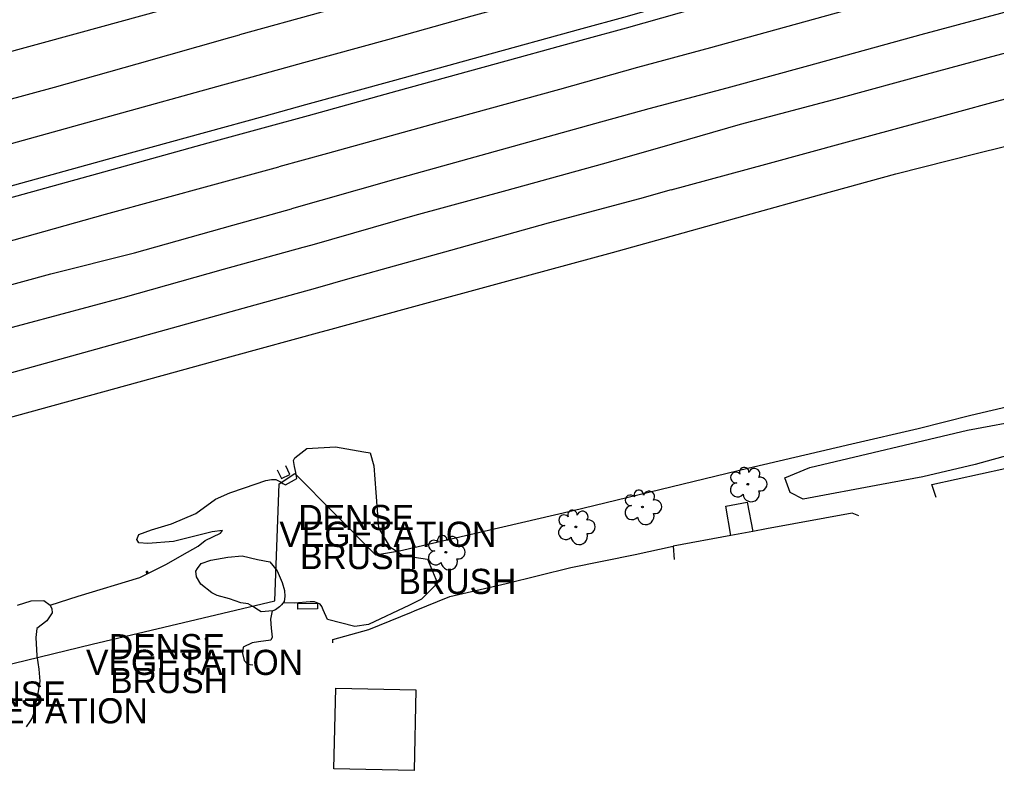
# Model space of a CAD drawing. Extents: x 2129547 to 2134906, y 657330 to 659734.
# Drawn here: x 2130826.3 to 2131098, y 657907.3 to 658118.5 of the extents above; entities that cross this region are included whole.
import ezdxf

# ---------------------------------------------------------------- set-up
doc = ezdxf.new("R2010")
doc.units = 0
for name, color, linetype in [('BD_X_Building', 7, 'Continuous'), ('Default', 7, 'Continuous'), ('DR_X_Culvert', 7, 'Continuous'), ('DR_X_Drainage_Area', 7, 'Continuous'), ('PM_X_Edge_Line', 7, 'Continuous'), ('PM_X_Lane_Line', 7, 'Continuous'), ('PM_X_LaneDOT', 7, 'Continuous'), ('PV_X_Driveway', 7, 'Continuous'), ('PV_X_EOP2', 7, 'Continuous'), ('PV_X_Parking_Lot', 7, 'Continuous'), ('RD_X_Concrete_Barrier', 7, 'Continuous'), ('RD_X_Concrete_Pad', 7, 'Continuous'), ('RD_X_Fence', 7, 'Continuous'), ('RD_X_Noise_Wall', 7, 'Continuous'), ('VG_X_Cells', 7, 'Continuous'), ('VG_X_Shrub_Line_Lt', 7, 'Continuous'), ('VG_X_Text', 7, 'Continuous'), ('VG_X_Tree_Line_Lt', 7, 'Continuous')]:
    doc.layers.add(name, color=color, linetype=linetype)

# ---------------------------------------------------------------- blocks, each defined once
blk = doc.blocks.new('TREE')
at = {"layer": 'VG_X_Cells'}
blk.add_circle((0, 0), 0.00305, dxfattribs=at)
for centre, radius, start, end in [((-0.042, 0.0237), 0.0187, 39.0625, 279.5412), ((-0.0125, 0.0428), 0.0167, 354.0047, 205.9741), ((0.0232, 0.0359), 0.0197, 323.83, 165.0376), ((-0.0362, -0.0197), 0.0251, 96.1722, 320.5737), ((0.0439, 0.0005), 0.0243, 259.1453, 101.4596), ((0.012, -0.0331), 0.029, 184.9476, 19.4572)]:
    blk.add_arc(centre, radius, start, end, dxfattribs=at)
blk = doc.blocks.new('PIPE')
at = {"layer": 'Default'}
for p, q in [((0.135, 0.067), (0, 0.067)), ((0, 0.067), (0, -0.067)), ((0, -0.067), (0.135, -0.067))]:
    blk.add_line(p, q, dxfattribs=at)

msp = doc.modelspace()

# ---------------------------------------------------------------- linework, layer by layer
at = {"layer": 'BD_X_Building'}
msp.add_lwpolyline([(2130914.24, 657932.69), (2130936.54, 657932.19), (2130936.04, 657909.78), (2130913.74, 657910.28)], close=True, dxfattribs=at)
at = {"layer": 'DR_X_Culvert'}
msp.add_lwpolyline([(2130903.73, 657956.21), (2130909.15, 657956.25), (2130909.16, 657954.68), (2130903.74, 657954.64)], close=True, dxfattribs=at)
at = {"layer": 'DR_X_Drainage_Area'}
msp.add_lwpolyline([(2131081.23, 657985.67), (2131079.99, 657989.28), (2131107.11, 657995.18), (2131138.13, 658002.86), (2131172.93, 658011.4), (2131184.68, 658014.24), (2131206.78, 658016.4), (2131235.33, 658019.59)], dxfattribs=at)
at = {"layer": 'PM_X_Edge_Line'}
for points in [[(2130891, 658102.57), (2130905.36, 658106.57), (2130928.7, 658112.95), (2130952.19, 658119.5), (2130974.68, 658125.71), (2130991.22, 658130.21), (2131011.99, 658135.88), (2131037.88, 658143.01), (2131060.83, 658149.3), (2131082.78, 658155.22), (2131106.25, 658161.71), (2131128.24, 658167.69), (2131156.14, 658175.52), (2131181.21, 658182.49), (2131205.87, 658189.24), (2131228.59, 658195.53), (2131252.79, 658202.27), (2131273.67, 658208.13), (2131298.68, 658214.86), (2131324.12, 658221.75), (2131348.82, 658228.57), (2131375.1, 658235.74), (2131400.81, 658242.88)], [(2131391.93, 658213.4), (2131368, 658206.91), (2131341.78, 658199.75), (2131315.24, 658192.47), (2131285.72, 658184.3), (2131257.55, 658176.45), (2131231.68, 658169.56), (2131212.62, 658164.32), (2131190.64, 658158.19), (2131169.84, 658152.49), (2131145.7, 658145.83), (2131125.75, 658140.27), (2131100.74, 658133.28), (2131080.69, 658127.69), (2131055.04, 658120.76), (2131018.49, 658110.67), (2130998.15, 658105.13), (2130976.5, 658099.09), (2130942.37, 658089.65), (2130912.01, 658081.31), (2130898.43, 658077.6)], [(2129783, 657797.65), (2129820.8, 657807.78), (2129922.27, 657836.17), (2129994.45, 657856.25), (2130028.21, 657865.49), (2130093.84, 657883.42), (2130153.98, 657899.99), (2130199.12, 657912.39), (2130249.09, 657926.31), (2130302.49, 657941.01), (2130341.07, 657951.58), (2130345.17, 657952.7), (2130404.65, 657969.17), (2130458.77, 657984.04), (2130511.95, 657998.61), (2130564.35, 658012.89), (2130611.28, 658025.79), (2130665.46, 658040.53), (2130717.36, 658054.84), (2130762.68, 658067.32), (2130806.63, 658079.2), (2130851.4, 658091.68), (2130882.88, 658100.31), (2130891, 658102.57)], [(2130911.96, 658032.18), (2130933.97, 658038.2), (2130961.85, 658045.78), (2130991.21, 658053.76), (2131010.83, 658059.23), (2131028.09, 658064.06), (2131048.8, 658069.77), (2131070.04, 658075.58), (2131092.36, 658081.28), (2131108.42, 658085.27)], [(2129782.31, 657770.56), (2129838.02, 657785.8), (2129918.94, 657807.73), (2130006.57, 657832.43), (2130060.5, 657847.21), (2130112.38, 657861.87), (2130166.66, 657876.43), (2130223.01, 657891.92), (2130282.32, 657908.07), (2130309.12, 657915.87), (2130347.7, 657926.43), (2130352.07, 657927.63), (2130411.57, 657944.11), (2130465.65, 657958.97), (2130518.8, 657973.53), (2130571.22, 657987.81), (2130618.14, 658000.71), (2130672.33, 658015.45), (2130724.27, 658029.78), (2130769.53, 658042.24), (2130813.51, 658054.13), (2130850.23, 658064.39), (2130880.11, 658072.6), (2130898.43, 658077.6)], [(2130514.96, 657935.23), (2130533.56, 657939.51), (2130548.13, 657942.33), (2130572.12, 657946.01), (2130593.17, 657948.82), (2130613.14, 657951.57), (2130630.34, 657955.2), (2130643.38, 657958.22), (2130656.02, 657961.69), (2130694.77, 657972.7), (2130735.95, 657984.14), (2130780.51, 657996.29), (2130819.12, 658006.73), (2130865.97, 658019.55), (2130885.83, 658025.06), (2130910.2, 658031.7), (2130911.96, 658032.18)]]:
    msp.add_lwpolyline(points, dxfattribs=at)
at = {"layer": 'PM_X_Lane_Line'}
for points in [[(2131394.23, 658253.22), (2131371.64, 658247.1), (2131347.48, 658240.52), (2131325.08, 658234.28), (2131302.56, 658228.11), (2131279.27, 658221.78), (2131255.34, 658215.2), (2131230.51, 658208.32), (2131202.78, 658200.44), (2131175.2, 658193.07), (2131142.99, 658184.04), (2131119.15, 658177.56), (2131092.27, 658170.26), (2131066.31, 658163.11), (2131037.76, 658155.51), (2131013.74, 658149.02), (2130988.03, 658141.76), (2130968.64, 658136.39), (2130940.36, 658128.62), (2130910.43, 658120.51), (2130887.53, 658114.21)], [(2131398.2, 658202.88), (2131377.59, 658197.24), (2131355.03, 658191.01), (2131329.48, 658184), (2131308.98, 658178.3), (2131287.17, 658172.05), (2131268.54, 658166.95), (2131249.14, 658161.71), (2131232.12, 658156.84), (2131210.13, 658150.71), (2131191.34, 658145.6), (2131170.47, 658139.83), (2131150.51, 658134.32), (2131128.13, 658128.26), (2131104.27, 658121.56), (2131076.93, 658114.27), (2131045.67, 658105.64), (2131023.04, 658099.46), (2131001.31, 658093.68), (2130986.21, 658089.5), (2130954.6, 658080.73), (2130930.95, 658074.11), (2130910.13, 658068.18), (2130901.91, 658065.91)], [(2131411.36, 658195.07), (2131385.77, 658188.02), (2131365.07, 658182.24), (2131339.74, 658175.46), (2131317.81, 658169.03), (2131291.94, 658161.94), (2131264.7, 658154.39), (2131240.9, 658147.6), (2131216.24, 658140.85), (2131193.46, 658134.43), (2131170.64, 658127.88), (2131144.22, 658120.81), (2131121.64, 658114.69), (2131098.02, 658108.51), (2131078.46, 658103.25), (2131054.06, 658096.57), (2131026.75, 658089.3), (2131004.3, 658082.86), (2130988.32, 658078.33), (2130961.86, 658070.94), (2130936.23, 658064.05), (2130907.59, 658055.8), (2130905.13, 658055.12)], [(2130517.26, 658025.11), (2130555.6, 658035.62), (2130596.09, 658046.96), (2130635.43, 658057.75), (2130673, 658068.21), (2130712.86, 658079.14), (2130754.47, 658090.52), (2130796.26, 658102.11), (2130842.82, 658114.83), (2130877.34, 658124.38), (2130883.95, 658126.23)], [(2130499.23, 658007.56), (2130538.61, 658018.28), (2130576.6, 658028.77), (2130618.67, 658040.36), (2130652.58, 658049.68), (2130692.07, 658060.48), (2130730.09, 658071.06), (2130768.24, 658081.36), (2130807.99, 658092.09), (2130836.01, 658099.68), (2130859, 658106.14), (2130884.83, 658113.47), (2130887.53, 658114.21)], [(2130526.03, 657962.85), (2130563.47, 657973.17), (2130601.11, 657983.57), (2130640.45, 657994.25), (2130678.58, 658004.73), (2130718.03, 658015.65), (2130757.3, 658026.31), (2130795.99, 658037.18), (2130835.05, 658047.79), (2130858.29, 658053.7), (2130885.63, 658061.39), (2130901.91, 658065.91)], [(2130905.13, 658055.12), (2130882.94, 658049.03), (2130855.07, 658041.17), (2130792.06, 658024.31), (2130751.21, 658013.06), (2130713.04, 658002.57), (2130674.42, 657991.9), (2130634.64, 657981.1), (2130596.28, 657970.59), (2130557.28, 657959.92), (2130518.18, 657949.28)]]:
    msp.add_lwpolyline(points, dxfattribs=at)
at = {"layer": 'PM_X_LaneDOT'}
for points in [[(2131007.54, 658071.14), (2131033.85, 658078.34), (2131056.59, 658084.53), (2131076.06, 658089.79), (2131097.73, 658095.69), (2131119.36, 658101.43), (2131140.64, 658107.17), (2131161.55, 658113.24)], [(2131007.54, 658071.14), (2130998.74, 658068.68), (2130973.29, 658061.89), (2130946.17, 658054.29), (2130918.18, 658046.48), (2130908.51, 658043.78)], [(2130908.51, 658043.78), (2130890.08, 658038.64), (2130533.56, 657939.51)]]:
    msp.add_lwpolyline(points, dxfattribs=at)
at = {"layer": 'PV_X_Driveway'}
for points in [[(2130935.32, 657953.77), (2130936.2, 657954.12), (2130946, 657958.15), (2130961.64, 657961.75), (2130979.67, 657966.18), (2130997.56, 657969.82), (2131008.07, 657972.13)], [(2130913.45, 657945.25), (2130913.43, 657946.24), (2130923.46, 657948.99), (2130935.32, 657953.77)]]:
    msp.add_lwpolyline(points, dxfattribs=at)
at = {"layer": 'PV_X_EOP2'}
for points in [[(2130891, 658102.57), (2130905.36, 658106.57), (2130928.7, 658112.95), (2130952.19, 658119.5), (2130974.68, 658125.71), (2130991.22, 658130.21), (2131011.99, 658135.88), (2131037.88, 658143.01), (2131060.83, 658149.3), (2131082.78, 658155.22), (2131106.25, 658161.71), (2131128.24, 658167.69), (2131156.14, 658175.52), (2131181.21, 658182.49), (2131205.87, 658189.24), (2131228.59, 658195.53), (2131252.79, 658202.27), (2131273.67, 658208.13), (2131298.68, 658214.86), (2131324.12, 658221.75), (2131348.82, 658228.57), (2131375.1, 658235.74), (2131400.81, 658242.88)], [(2131391.93, 658213.4), (2131368, 658206.91), (2131341.78, 658199.75), (2131315.24, 658192.47), (2131285.72, 658184.3), (2131257.55, 658176.45), (2131231.68, 658169.56), (2131212.62, 658164.32), (2131190.64, 658158.19), (2131169.84, 658152.49), (2131145.7, 658145.83), (2131125.75, 658140.27), (2131100.74, 658133.28), (2131080.69, 658127.69), (2131055.04, 658120.76), (2131018.49, 658110.67), (2130998.15, 658105.13), (2130976.5, 658099.09), (2130942.37, 658089.65), (2130912.01, 658081.31), (2130898.43, 658077.6)], [(2129783, 657797.65), (2129820.8, 657807.78), (2129922.27, 657836.17), (2129994.45, 657856.25), (2130028.21, 657865.49), (2130093.84, 657883.42), (2130153.98, 657899.99), (2130199.12, 657912.39), (2130249.09, 657926.31), (2130302.49, 657941.01), (2130341.07, 657951.58), (2130345.17, 657952.7), (2130404.65, 657969.17), (2130458.77, 657984.04), (2130511.95, 657998.61), (2130564.35, 658012.89), (2130611.28, 658025.79), (2130665.46, 658040.53), (2130717.36, 658054.84), (2130762.68, 658067.32), (2130806.63, 658079.2), (2130851.4, 658091.68), (2130882.88, 658100.31), (2130891, 658102.57)], [(2130911.96, 658032.18), (2130933.97, 658038.2), (2130961.85, 658045.78), (2130991.21, 658053.76), (2131010.83, 658059.23), (2131028.09, 658064.06), (2131048.8, 658069.77), (2131070.04, 658075.58), (2131092.36, 658081.28), (2131108.42, 658085.27), (2131129.89, 658090.28), (2131149.34, 658094.56), (2131164.37, 658097.66)], [(2129782.31, 657770.56), (2129838.02, 657785.8), (2129918.94, 657807.73), (2130006.57, 657832.43), (2130060.5, 657847.21), (2130112.38, 657861.87), (2130166.66, 657876.43), (2130223.01, 657891.92), (2130282.32, 657908.07), (2130309.12, 657915.87), (2130347.7, 657926.43), (2130352.07, 657927.63), (2130411.57, 657944.11), (2130465.65, 657958.97), (2130518.8, 657973.53), (2130571.22, 657987.81), (2130618.14, 658000.71), (2130672.33, 658015.45), (2130724.27, 658029.78), (2130769.53, 658042.24), (2130813.51, 658054.13), (2130850.23, 658064.39), (2130880.11, 658072.6), (2130898.43, 658077.6)], [(2130514.96, 657935.23), (2130533.56, 657939.51), (2130548.13, 657942.33), (2130572.12, 657946.01), (2130593.17, 657948.82), (2130613.14, 657951.57), (2130630.34, 657955.2), (2130643.38, 657958.22), (2130656.02, 657961.69), (2130694.77, 657972.7), (2130735.95, 657984.14), (2130780.51, 657996.29), (2130819.12, 658006.73), (2130865.97, 658019.55), (2130885.83, 658025.06), (2130910.2, 658031.7), (2130911.96, 658032.18)]]:
    msp.add_lwpolyline(points, dxfattribs=at)
at = {"layer": 'PV_X_Parking_Lot'}
msp.add_lwpolyline([(2131059.67, 657980.58), (2131057.85, 657981.27), (2131034.07, 657976.95), (2131030.19, 657976.23), (2131024.14, 657975.11), (2131008.07, 657972.13), (2131008.32, 657968.47)], dxfattribs=at)
at = {"layer": 'RD_X_Concrete_Barrier'}
for points in [[(2131391.74, 658229.13), (2131379.32, 658225.19), (2131359.92, 658219.83), (2131338.36, 658213.96), (2131312.24, 658206.8), (2131285.52, 658199.37), (2131257.25, 658191.69), (2131234.72, 658185.34), (2131209.47, 658178.52), (2131183.51, 658171.23), (2131159.15, 658164.59), (2131135.07, 658158.08), (2131111.97, 658151.63), (2131085.68, 658144.48), (2131061.03, 658137.57), (2131037, 658130.96), (2131013.95, 658124.67), (2130994.29, 658119.1), (2130982.69, 658115.91), (2130954.42, 658108.17), (2130930.56, 658101.55), (2130905.86, 658094.77), (2130894.27, 658091.58)], [(2130895.13, 658088.7), (2130906.66, 658091.87), (2130931.36, 658098.66), (2130955.21, 658105.28), (2130983.48, 658113.02), (2130995.09, 658116.21), (2131014.76, 658121.78), (2131037.79, 658128.06), (2131061.83, 658134.68), (2131086.48, 658141.59), (2131112.76, 658148.74), (2131135.87, 658155.19), (2131159.93, 658161.69), (2131184.31, 658168.34), (2131210.27, 658175.63), (2131235.52, 658182.45), (2131258.05, 658188.8), (2131286.32, 658196.47), (2131313.04, 658203.91), (2131339.15, 658211.07), (2131360.71, 658216.94), (2131380.03, 658222.28), (2131393.19, 658225.09)], [(2130894.27, 658091.58), (2130878, 658087.11), (2130853.36, 658080.31), (2130816.1, 658070.01), (2130782.91, 658060.82), (2130737.86, 658048.46), (2130695.16, 658036.46), (2130654.54, 658025.52), (2130616.29, 658015.21), (2130565.99, 658001.27), (2130519.98, 657988.71)], [(2130520.77, 657985.82), (2130566.78, 657998.38), (2130617.08, 658012.31), (2130655.32, 658022.62), (2130695.96, 658033.57), (2130738.66, 658045.57), (2130783.7, 658057.93), (2130816.89, 658067.12), (2130854.16, 658077.41), (2130878.8, 658084.22), (2130895.13, 658088.7)]]:
    msp.add_lwpolyline(points, dxfattribs=at)
at = {"layer": 'RD_X_Concrete_Pad'}
msp.add_lwpolyline([(2131024.14, 657975.11), (2131022.68, 657983.24), (2131028.64, 657984.35), (2131030.19, 657976.23)], dxfattribs=at)
at = {"layer": 'RD_X_Fence'}
msp.add_lwpolyline([(2130372.76, 657831.4), (2130401.89, 657841.24), (2130444.91, 657852.66), (2130493.65, 657863.34), (2130547.6, 657875.39), (2130589.68, 657885.4), (2130636.62, 657895.64), (2130749.57, 657921.43), (2130795.47, 657932.48), (2130846.52, 657944.86), (2130897.31, 657956.97), (2130898.55, 657989.46), (2130902.91, 657992.37), (2130925.34, 657969.73), (2130931.96, 657970.88)], dxfattribs=at)
at = {"layer": 'RD_X_Noise_Wall'}
msp.add_lwpolyline([(2130931.96, 657970.88), (2130980.32, 657982.07), (2131028.87, 657993.85), (2131057.77, 658000.57), (2131076.18, 658004.83), (2131090.82, 658008.54), (2131108.69, 658012.68), (2131119.07, 658015.09), (2131137.42, 658019.48), (2131157.38, 658024.08), (2131175.99, 658028.56), (2131194.4, 658032.9), (2131206.33, 658035.77), (2131208.58, 658036.27), (2131223.29, 658038.63), (2131234.65, 658040.24), (2131251.99, 658042.15), (2131266.67, 658043.72), (2131282.64, 658045.38), (2131301.91, 658047.28), (2131315.35, 658048.67), (2131352.59, 658052.69), (2131374.52, 658055.12), (2131396.24, 658057.26)], dxfattribs=at)
at = {"layer": 'VG_X_Cells'}
for centre in [(2130861.78, 657964.89), (2130878.15, 657946.38)]:
    msp.add_circle(centre, 0.012, dxfattribs=at)
for centre, radius, start, end in [((2130861.62, 657964.98), 0.0735, 39.0625, 279.5412), ((2130861.64, 657964.81), 0.0987, 96.1722, 320.5737), ((2130861.73, 657965.06), 0.0658, 354.0047, 205.9741), ((2130861.88, 657965.03), 0.0776, 323.83, 165.0376), ((2130861.96, 657964.89), 0.0957, 259.1453, 101.4596), ((2130861.83, 657964.76), 0.114, 184.9476, 19.4572), ((2130877.98, 657946.47), 0.0735, 39.0625, 279.5412), ((2130878.01, 657946.3), 0.0987, 96.1722, 320.5737), ((2130878.1, 657946.55), 0.0658, 354.0047, 205.9741), ((2130878.2, 657946.25), 0.114, 184.9476, 19.4572), ((2130878.24, 657946.52), 0.0776, 323.83, 165.0376), ((2130878.32, 657946.38), 0.0957, 259.1453, 101.4596)]:
    msp.add_arc(centre, radius, start, end, dxfattribs=at)
at = {"layer": 'VG_X_Shrub_Line_Lt'}
for points in [[(2130834.85, 657955.72), (2130842.65, 657958.21), (2130859.8, 657963.43), (2130867.19, 657967.16), (2130871.52, 657969.6), (2130876.03, 657972.13), (2130877.94, 657973.68), (2130882.22, 657975.74), (2130882.78, 657976.49), (2130879.9, 657976.08), (2130869.12, 657973.43), (2130861.96, 657972.83), (2130859.53, 657973.1), (2130858.95, 657973.99), (2130859.53, 657975.34), (2130862.99, 657976.63), (2130868.59, 657978.31), (2130875.36, 657981.25), (2130880.84, 657985.21), (2130884.81, 657986.92), (2130888.87, 657988.37), (2130894.8, 657990.41), (2130896.38, 657990.69), (2130897.59, 657990.64), (2130898.86, 657990.01), (2130899.55, 657989.53), (2130900.31, 657989.21), (2130902.8, 657990.56), (2130903.43, 657990.95), (2130903.18, 657992.57), (2130902.83, 657994.25), (2130902.48, 657995.97), (2130902.87, 657996.66), (2130906.19, 657999.27), (2130914.17, 657999.72), (2130922.03, 657998.37), (2130923.79, 657998.07), (2130924.83, 657994.49), (2130925.41, 657987.03), (2130926.17, 657977.22), (2130929.16, 657972.06), (2130930.04, 657971.47), (2130932.99, 657969.52), (2130939.75, 657968.54), (2130942.57, 657961.88), (2130938.11, 657957.41), (2130934.72, 657955.78), (2130923.36, 657950.33), (2130919.53, 657949.82), (2130911.94, 657951.79), (2130910.75, 657954.48), (2130910.4, 657955.39), (2130909.89, 657956.04), (2130908.37, 657956.7), (2130907.17, 657956.7), (2130902.78, 657956.29), (2130899.63, 657956.38)], [(2130896.54, 657954.13), (2130896.09, 657951.84), (2130896.28, 657949.32), (2130896.62, 657946.85), (2130896.25, 657946.03), (2130892.76, 657945.56), (2130891.04, 657945.28), (2130888.56, 657944.1), (2130888.36, 657942.29), (2130888.75, 657940.36), (2130889.72, 657939.34), (2130891.17, 657939.16)]]:
    msp.add_lwpolyline(points, dxfattribs=at)
at = {"layer": 'VG_X_Tree_Line_Lt'}
for points in [[(2131106.84, 658007.5), (2131137.48, 658013.79), (2131150.96, 658017.34), (2131156.06, 658017.66), (2131160.36, 658014.23), (2131158.71, 658011.58), (2131115.74, 658001.37), (2131092.01, 657994.84), (2131077.49, 657991.38), (2131065.97, 657989.24), (2131044.21, 657985.16), (2131040.57, 657987.06), (2131039.11, 657991.16), (2131046.06, 657994.02), (2131089.93, 658004.34), (2131106.84, 658007.5)], [(2130825.76, 657955.71), (2130829.61, 657956.91), (2130833.09, 657957.06), (2130834.85, 657955.72), (2130835.32, 657954.7), (2130835.43, 657953.6), (2130833.94, 657951.37), (2130831.14, 657949.24), (2130830.86, 657946.79), (2130831.18, 657941.63), (2130831.68, 657937.98), (2130831.99, 657934.66), (2130831.26, 657930.07), (2130830.7, 657927.95), (2130830.3, 657925.83), (2130829.87, 657924.42), (2130829.24, 657923.41), (2130828.19, 657921.95)]]:
    msp.add_lwpolyline(points, dxfattribs=at)
msp.add_lwpolyline([(2130893.53, 657953.93), (2130892.77, 657954.32), (2130891.16, 657955.35), (2130889.95, 657956.07), (2130887.83, 657956.43), (2130884.74, 657957.48), (2130881.29, 657958.46), (2130879.79, 657959.2), (2130876.76, 657961.53), (2130875.58, 657963.57), (2130875.34, 657965.21), (2130875.85, 657965.97), (2130876.85, 657967.3), (2130879.57, 657968.28), (2130884.29, 657969.08), (2130888.25, 657969.41), (2130892.48, 657968.42), (2130895.97, 657967.79), (2130898, 657965.27), (2130899.32, 657962.03), (2130899.98, 657959.8), (2130900.09, 657958.1), (2130899.9, 657956.73), (2130899.2, 657955.84), (2130898.65, 657955.24), (2130897.47, 657954.48), (2130896.75, 657954.14)], close=True, dxfattribs=at)

# ---------------------------------------------------------------- block references
at = {"layer": 'DR_X_Culvert', "xscale": 19.685000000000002, "yscale": 19.685, "rotation": 115.35622509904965}
msp.add_blockref('PIPE', (2130900.33, 657991.53), dxfattribs=at)
at = {"layer": 'VG_X_Cells', "xscale": 78.74000000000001, "yscale": 78.74000000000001}
for p in [(2131028.83, 657989.35), (2130999.53, 657983.03), (2130981.04, 657977.48), (2130944.87, 657970.44)]:
    msp.add_blockref('TREE', p, dxfattribs=at)

# ---------------------------------------------------------------- texts
at = {"layer": 'VG_X_Text'}
for s, p in [('DENSE', (2130903.84, 657976.59)), ('VEGETATION', (2130898.59, 657971.94)), ('BRUSH', (2130904.31, 657965.75)), ('BRUSH', (2130931.71, 657958.84)), ('DENSE', (2130851.19, 657940.7)), ('VEGETATION', (2130844.82, 657936.34)), ('BRUSH', (2130851.52, 657931.31)), ('DENSE', (2130806.91, 657927.53)), ('VEGETATION', (2130801.65, 657922.88))]:
    msp.add_text(s, height=7, dxfattribs=at).set_placement(p)

doc.saveas('drawing.dxf')
